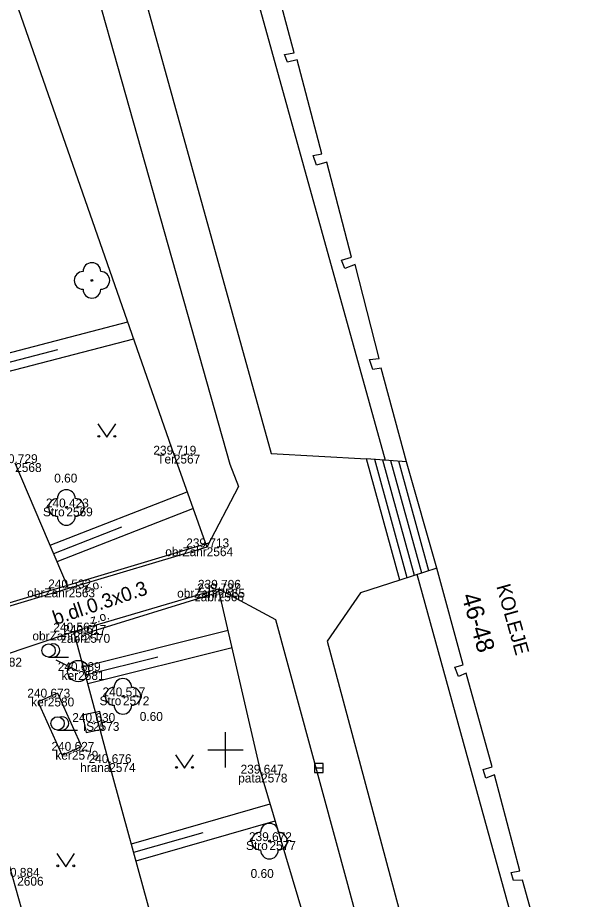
# Model space of a CAD drawing. Extents: x -599098 to -598820, y -1159597 to -1158744.
# Drawn here: x -598961.7 to -598929, y -1159058.42 to -1159008.74 of the extents above; entities that cross this region are included whole.
import ezdxf

# ---------------------------------------------------------------- set-up
doc = ezdxf.new("R2010")
doc.units = 0
for name, color, linetype in [('body', 7, 'Continuous'), ('budovy', 7, 'Continuous'), ('druh pozemku stromy', 7, 'Continuous'), ('hektometrická síť', 7, 'Continuous'), ('kresba', 7, 'Continuous'), ('kódy bodů', 7, 'Continuous'), ('popisy', 7, 'Continuous'), ('popisy budov', 7, 'Continuous'), ('výšky bodů', 7, 'Continuous'), ('značky IS', 7, 'Continuous'), ('zábradlí', 7, 'Continuous'), ('čísla bodů', 7, 'Continuous')]:
    doc.layers.add(name, color=color, linetype=linetype)

msp = doc.modelspace()

# ---------------------------------------------------------------- linework, layer by layer
at = {"layer": 'body'}
for p, q in [((-598952.909, -1159033.366), (-598952.909, -1159033.366)), ((-598958.96, -1159036.34), (-598958.96, -1159036.34)), ((-598951.058, -1159038.586), (-598951.058, -1159038.586)), ((-598958.831, -1159040.902), (-598958.831, -1159040.902)), ((-598950.388, -1159040.921), (-598950.388, -1159040.921)), ((-598950.444, -1159041.127), (-598950.444, -1159041.127)), ((-598958.538, -1159043.331), (-598958.538, -1159043.331)), ((-598957.98, -1159043.466), (-598957.98, -1159043.466)), ((-598958.293, -1159045.559), (-598958.293, -1159045.559)), ((-598960.005, -1159047.052), (-598960.005, -1159047.052)), ((-598955.773, -1159046.983), (-598955.773, -1159046.983)), ((-598957.459, -1159048.429), (-598957.459, -1159048.429)), ((-598958.647, -1159050.051), (-598958.647, -1159050.051)), ((-598956.548, -1159050.744), (-598956.548, -1159050.744)), ((-598947.997, -1159051.337), (-598947.997, -1159051.337)), ((-598947.525, -1159055.14), (-598947.525, -1159055.14))]:
    msp.add_line(p, q, dxfattribs=at)
at = {"layer": 'budovy'}
msp.add_lwpolyline([(-598931.82, -1159062.55), (-598933.28, -1159057.34), (-598933.78, -1159057.36), (-598933.92, -1159056.9), (-598933.42, -1159056.81), (-598934.86, -1159051.41), (-598935.33, -1159051.6), (-598935.49, -1159051.11), (-598934.99, -1159050.96), (-598936.44, -1159045.67), (-598936.87, -1159045.86), (-598937.08, -1159045.34), (-598936.62, -1159045.21), (-598938.1, -1159039.77), (-598939.8, -1159033.77), (-598941.23, -1159028.49), (-598941.71, -1159028.57), (-598941.89, -1159028.01), (-598941.34, -1159027.94), (-598942.69, -1159022.66), (-598943.28, -1159022.87), (-598943.46, -1159022.4), (-598942.91, -1159022.24), (-598944.29, -1159016.88), (-598944.87, -1159017.05), (-598945.07, -1159016.52), (-598944.57, -1159016.42), (-598945.96, -1159011.13), (-598946.51, -1159011.26), (-598946.67, -1159010.82), (-598946.13, -1159010.72), (-598947.55, -1159005.4)], dxfattribs=at)
at = {"layer": 'druh pozemku stromy'}
for p, q in [((-598959.961, -1159044.778), (-598958.837, -1159044.778)), ((-598959.546, -1159044.924), (-598958.293, -1159045.559)), ((-598959.458, -1159046.804), (-598960.005, -1159047.052)), ((-598959.458, -1159046.804), (-598958.1, -1159049.803)), ((-598960.005, -1159047.052), (-598960.551, -1159047.299)), ((-598959.193, -1159050.298), (-598960.551, -1159047.299)), ((-598959.453, -1159048.884), (-598958.329, -1159048.884)), ((-598958.647, -1159050.051), (-598958.1, -1159049.803)), ((-598959.193, -1159050.298), (-598958.647, -1159050.051))]:
    msp.add_line(p, q, dxfattribs=at)
for points in [[(-598957.181, -1159031.634), (-598956.681, -1159032.384), (-598956.181, -1159031.634)], [(-598952.806, -1159050.287), (-598952.306, -1159051.037), (-598951.806, -1159050.287)], [(-598959.493, -1159055.835), (-598958.993, -1159056.585), (-598958.493, -1159055.835)]]:
    msp.add_lwpolyline(points, dxfattribs=at)
for centre, radius in [((-598957.52, -1159023.55), 0.05), ((-598957.132, -1159032.334), 0.05), ((-598956.232, -1159032.334), 0.05), ((-598958.96, -1159036.34), 0.05), ((-598959.961, -1159044.402), 0.375), ((-598958.293, -1159045.559), 0.6), ((-598955.773, -1159046.983), 0.05), ((-598959.453, -1159048.508), 0.375), ((-598952.756, -1159050.987), 0.05), ((-598951.857, -1159050.987), 0.05), ((-598947.525, -1159055.14), 0.05), ((-598959.443, -1159056.535), 0.05), ((-598958.544, -1159056.535), 0.05)]:
    msp.add_circle(centre, radius, dxfattribs=at)
for centre, radius, start, end in [((-598957.52, -1159023.05), 0.5, 0, 180), ((-598958.02, -1159023.55), 0.5, 90, 270), ((-598957.02, -1159023.55), 0.5, 270, 90), ((-598957.52, -1159024.05), 0.5, 180, 0), ((-598958.96, -1159035.84), 0.5, 0, 180), ((-598959.46, -1159036.34), 0.5, 90, 270), ((-598958.46, -1159036.34), 0.5, 270, 90), ((-598958.96, -1159036.84), 0.5, 180, 0), ((-598959.711, -1159044.402), 0.375, 249.4944, 109.0474), ((-598955.773, -1159046.483), 0.5, 0, 180), ((-598956.273, -1159046.983), 0.5, 90, 270), ((-598955.273, -1159046.983), 0.5, 270, 90), ((-598955.773, -1159047.483), 0.5, 180, 0), ((-598959.203, -1159048.508), 0.375, 249.4944, 109.0474), ((-598947.525, -1159054.64), 0.5, 0, 180), ((-598948.025, -1159055.14), 0.5, 90, 270), ((-598947.025, -1159055.14), 0.5, 270, 90), ((-598947.525, -1159055.64), 0.5, 180, 0)]:
    msp.add_arc(centre, radius, start, end, dxfattribs=at)
at = {"layer": 'hektometrická síť'}
for p, q in [((-598950, -1159051), (-598950, -1159049)), ((-598951, -1159050), (-598949, -1159050))]:
    msp.add_line(p, q, dxfattribs=at)
at = {"layer": 'kresba'}
for p, q in [((-598955.513, -1159025.905), (-598963.289, -1159027.938)), ((-598955.179, -1159026.86), (-598963.051, -1159028.91)), ((-598959.467, -1159027.454), (-598963.171, -1159028.421)), ((-598952.909, -1159033.366), (-598951.058, -1159038.586)), ((-598958.831, -1159040.902), (-598961.842, -1159033.843)), ((-598939.8, -1159033.77), (-598942.05, -1159033.61)), ((-598940.18, -1159040.43), (-598942.05, -1159033.61)), ((-598939.77, -1159040.3), (-598941.59, -1159033.64)), ((-598939.36, -1159040.17), (-598941.14, -1159033.68)), ((-598938.95, -1159040.04), (-598940.68, -1159033.71)), ((-598938.54, -1159039.91), (-598940.23, -1159033.74)), ((-598959.869, -1159038.466), (-598952.165, -1159035.461)), ((-598949.27, -1159035.17), (-598951.058, -1159038.586)), ((-598959.477, -1159039.387), (-598951.831, -1159036.404)), ((-598959.673, -1159038.927), (-598955.836, -1159037.429)), ((-598951.058, -1159038.586), (-598958.831, -1159040.902)), ((-598938.1, -1159039.77), (-598940.18, -1159040.43)), ((-598958.831, -1159040.902), (-598963.677, -1159042.368)), ((-598958.538, -1159043.331), (-598950.388, -1159040.921)), ((-598950.388, -1159040.921), (-598947.19, -1159042.65)), ((-598947.997, -1159051.337), (-598950.388, -1159040.921)), ((-598962.946, -1159044.807), (-598958.538, -1159043.331)), ((-598956.548, -1159050.744), (-598958.538, -1159043.331)), ((-598958.01, -1159045.294), (-598949.85, -1159043.262)), ((-598957.751, -1159046.26), (-598949.626, -1159044.237)), ((-598957.881, -1159045.777), (-598953.809, -1159044.763)), ((-598964.644, -1159047.801), (-598959.455, -1159066.177)), ((-598952.81, -1159064.352), (-598956.548, -1159050.744)), ((-598944.816, -1159061.959), (-598947.997, -1159051.337)), ((-598955.299, -1159055.288), (-598947.485, -1159053.045)), ((-598955.034, -1159056.252), (-598947.198, -1159054.003)), ((-598955.167, -1159055.77), (-598951.254, -1159054.647))]:
    msp.add_line(p, q, dxfattribs=at)
for points in [[(-598940.99, -1159033.69), (-598957.39, -1158974.51), (-598957.66, -1158973.64)], [(-598966.43, -1158980.85), (-598962.03, -1158981.13), (-598956.78, -1158979.59), (-598954.5, -1158987.51), (-598959.64, -1158989.19), (-598947.43, -1159033.31), (-598942.05, -1159033.61)], [(-598963.5, -1158985.24), (-598949.76, -1159033.91), (-598949.27, -1159035.17)], [(-598965.15, -1158985.55), (-598966.4, -1158994.71), (-598952.909, -1159033.366)], [(-598940.18, -1159040.43), (-598942.4, -1159041.16), (-598944.28, -1159043.88), (-598939.55, -1159061.52), (-598929.18, -1159098.6)], [(-598923.3, -1159097.62), (-598923.52, -1159097.05), (-598939.2, -1159040.12)], [(-598947.19, -1159042.65), (-598943.18, -1159057.36), (-598932.43, -1159097.3), (-598937.29, -1159107.63)]]:
    msp.add_lwpolyline(points, dxfattribs=at)
at = {"layer": 'značky IS'}
for p, q in [((-598957.077, -1159047.834), (-598958.054, -1159048.047)), ((-598956.864, -1159048.811), (-598957.077, -1159047.834)), ((-598958.054, -1159048.047), (-598957.841, -1159049.024)), ((-598957.841, -1159049.024), (-598956.864, -1159048.811)), ((-598944.99, -1159051.02), (-598944.49, -1159051.02))]:
    msp.add_line(p, q, dxfattribs=at)
msp.add_lwpolyline([(-598944.99, -1159051.27), (-598944.49, -1159051.27), (-598944.49, -1159050.77), (-598944.99, -1159050.77)], close=True, dxfattribs=at)
at = {"layer": 'zábradlí'}
msp.add_line((-598957.98, -1159043.466), (-598950.444, -1159041.127), dxfattribs=at)
msp.add_lwpolyline([(-598967.413, -1159036.62), (-598966.425, -1159040.327), (-598963.647, -1159042.143), (-598950.934, -1159038.334)], dxfattribs=at)

# ---------------------------------------------------------------- texts
at = {"layer": 'druh pozemku stromy'}
for p in [(-598959.643, -1159034.937), (-598954.826, -1159048.366), (-598948.583, -1159057.212)]:
    msp.add_text('0.60', height=0.5, dxfattribs=at).set_placement(p)
at = {"layer": 'kódy bodů'}
for s, p in [('Ter', (-598953.842, -1159033.866)), ('Stro', (-598960.278, -1159036.84)), ('obrZahr', (-598953.391, -1159039.086)), ('obrZahr', (-598961.164, -1159041.402)), ('obrZahr', (-598952.721, -1159041.421)), ('zabr', (-598951.727, -1159041.627)), ('obrZahr', (-598960.871, -1159043.831)), ('zabr', (-598959.263, -1159043.966)), ('ker', (-598959.226, -1159046.059)), ('ker', (-598960.938, -1159047.552)), ('Stro', (-598957.091, -1159047.483)), ('IS', (-598958.028, -1159048.929)), ('ker', (-598959.58, -1159050.551)), ('hrana', (-598958.184, -1159051.244)), ('pata', (-598949.283, -1159051.837)), ('Stro', (-598948.843, -1159055.64))]:
    msp.add_text(s, height=0.5, dxfattribs=at).set_placement(p)
at = {"layer": 'popisy'}
for s, height, rotation, p in [('b.dl.0.3x0.3', 0.8, 18.5129, (-598959.572, -1159042.974)), ('z.o.', 0.5, 16.5917, (-598957.92, -1159041.152)), ('KOLEJE ', 0.8, 285.68, (-598934.753, -1159040.778)), ('z.o.', 0.5, 16.4732, (-598957.526, -1159042.927))]:
    msp.add_text(s, height=height, rotation=rotation, dxfattribs=at).set_placement(p)
at = {"layer": 'popisy budov'}
msp.add_text('46-48 ', height=1, rotation=286.38, dxfattribs=at).set_placement((-598936.72, -1159041.32))
at = {"layer": 'výšky bodů'}
for s, p in [('239.719', (-598954.061, -1159033.366)), ('240.729', (-598962.994, -1159033.843)), ('240.423', (-598960.112, -1159036.34)), ('239.713', (-598952.21, -1159038.586)), ('240.532', (-598959.983, -1159040.902)), ('239.706', (-598951.548, -1159040.921)), ('239.737', (-598951.596, -1159041.127)), ('240.567', (-598959.69, -1159043.331)), ('240.617', (-598959.132, -1159043.466)), ('240.689', (-598959.445, -1159045.559)), ('240.673', (-598961.157, -1159047.052)), ('240.517', (-598956.925, -1159046.983)), ('240.630', (-598958.625, -1159048.429)), ('240.627', (-598959.799, -1159050.051)), ('240.676', (-598957.708, -1159050.744)), ('239.647', (-598949.149, -1159051.337)), ('239.672', (-598948.677, -1159055.14)), ('240.884', (-598962.881, -1159057.15))]:
    msp.add_text(s, height=0.5, dxfattribs=at).set_placement(p)
at = {"layer": 'čísla bodů'}
for s, p in [('2567', (-598952.909, -1159033.866)), ('2568', (-598961.842, -1159034.343)), ('2569', (-598958.96, -1159036.84)), ('2564', (-598951.058, -1159039.086)), ('2563', (-598958.831, -1159041.402)), ('2565', (-598950.388, -1159041.421)), ('2566', (-598950.444, -1159041.627)), ('2571', (-598958.538, -1159043.831)), ('2570', (-598957.98, -1159043.966)), ('2582', (-598962.946, -1159045.307)), ('2581', (-598958.293, -1159046.059)), ('2580', (-598960.005, -1159047.552)), ('2572', (-598955.773, -1159047.483)), ('2573', (-598957.459, -1159048.929)), ('2579', (-598958.647, -1159050.551)), ('2574', (-598956.548, -1159051.244)), ('2578', (-598947.997, -1159051.837)), ('2577', (-598947.525, -1159055.64)), ('2606', (-598961.729, -1159057.65))]:
    msp.add_text(s, height=0.5, dxfattribs=at).set_placement(p)

doc.saveas('drawing.dxf')
